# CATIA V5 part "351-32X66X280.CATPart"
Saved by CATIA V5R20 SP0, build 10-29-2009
Part number: 351-32X66X280
Definition: NONE
Nomenclature: 351-32X66X280
Source: Unknown
Description: 351-32X66X280
Bounding box of the stored display mesh (mm): x -7 to 273, y -22.5 to 22.5, z -22.5 to 22.5
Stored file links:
  C:\Users\Utente\Desktop\IO LAVORO\3D X SITO CF\X SITO\PLASTICA\351\351-32X66X280.CATPart
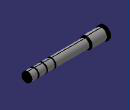
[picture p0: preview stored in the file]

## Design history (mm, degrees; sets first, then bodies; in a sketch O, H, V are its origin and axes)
Body1 "351-32X66X280" (main body)
  Solid1: solid without history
